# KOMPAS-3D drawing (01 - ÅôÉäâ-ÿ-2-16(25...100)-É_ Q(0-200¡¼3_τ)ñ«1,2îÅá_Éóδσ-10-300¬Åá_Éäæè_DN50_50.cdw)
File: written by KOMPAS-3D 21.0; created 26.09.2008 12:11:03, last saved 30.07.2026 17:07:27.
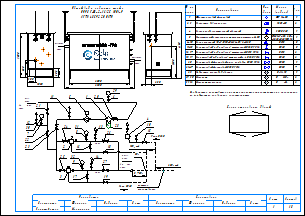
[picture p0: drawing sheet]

Sheets 1-2: A3, landscape

Document properties: Наименование: Макро:21; Автор: RaskoAdmin; Форматы листов документа: 2xA3; Полное имя файла: \\ur38nt01\Departments\КТО\КБ ПУРДГ\Заявки\Прайс-лист на типовые шкафы ГРПШ\ПУРДГ_стандарт_30_04_2026\ПУРДГ с РДСК\ПУРДГ-Ш-2-16(25...100)-Р_ Q(0-200нм3_ч)до1,2МПа_Рвых-10-300кПа_РДСК_DN50_50.cdw

Title block, sheet 1: Наименование: Пункт учета газа / ПУГ-Ш-400-Р / ЛГТИ.485922.001ТУ; designation: ЛГТИ.03.4411141; sheet number: 1; Количество листов документа: 2; organisation: ООО "ЭЛЬСТЕР Газэлектроника"; Форматы листов документа: A3; stored path: C:\Рабочие документы\Компас\ПУГ\Схема.cdw; Разработал: Устинов; Проверил: Кошкин; Утвердил: Кошкин
Title block, sheet 2: sheet number: 2; stored path: D:\Рабочие документы\Заявки\ПУРДГ\ПУРДГ-ШУЭО-2-100-Р 4411220.cdw; designation, second copy: ЛГТИ.03.4411141-

Views: Вид 1, Вид 2
Referenced files: wcvoit.frw
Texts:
  Normal
  № на
  схеме
  Усл.
  обозн.
  Марка
  (модель)
  Кол.
  Фильтр газовый фланцевый
  ФГ 16-50
  Регулятор давления газа
  РДСК-50
  Клапан предохранительный сбросной
  КПС DN20
  Измерительный комплекс с ротационным счетчиком Ду50
  СГ-ЭК-Р-(0,2...2,0)-
  Кран кнопочный VE-РАСКО-НЗ-1,6-G1/2-М20
  DN15
  Кран шаровой "под приварку" штуцерный DN20 PN16
  DN20
  Кран шаровой "под приварку" штуцерный DN15 PN16
  Кран шаровой "под приварку" штуцерный п/п DN20 PN16
  Кран шаровой фланцевый с мех. приводом DN50 PN16
  Кран шаровой фланцевый DN50 PN16
  DN50
  Индикатор перепада давления
  Манометр
  Манометр-напоромер
  Delta 15
  0...     МПа
  0...     кПа
  Общий вид и габариты шкафа
  ПУРДГ-Ш-2-16(25...100)-Р
  Выход газа
  Вход газа
  logo-rasko-ge.png
  DN 1
  местное
  сопротивление
  Римп DN20
  Выход
  газа
  Р=     кПа
  Вход
  Р=       МПа
  PDI
  Схема открывания дверей
  Предприятие изготовитель может заменять комплектующие на аналогичные,
  не ухудшающие заявленных характеристик.
  Должность
  Конструктор
  Фамилия
  Подпись
  Дата
  Согласовано
  Максимкин
  Лист
  Листов
  POLYLINE_STYLE_0.18_RGB_0_0_0
  POLYLINE_STYLE_0.50_RGB_0_0_0
  POLYLINE_STYLE_0.34_RGB_0_0_0
  PHANTOM_RGB_0_0_0_SC_1_THICK_0.18
  K5LT_THIN_RGB_0_0_0_THICK_0.18
  K5LT32769_RGB_0_0_0_THICK_0.18
  K5LT12_RGB_0_0_0_SC_1_THICK_0.18
  K5LT_DASHED_RGB_0_0_0_SC_1_THICK_0.18
  ACISOTGL_RGB_0_0_0_SC_0.8_THICK_0.25
  CONTINUOUS_RGB_0_127_31_THICK_0.3
  CONTINUOUS_RGB_0_0_255_THICK_0.35
  CONTINUOUS_RGB_255_0_0_THICK_0.35
  POLYLINE_STYLE_0.25_RGB_0_0_0
  CONTINUOUS_RGB_0_0_0_THICK_0.5
  POLYLINE_STYLE_0.35_RGB_0_0_255
  CONTINUOUS_RGB_0_0_0_THICK_0.4
  CONTINUOUS_RGB_0_0_0_THICK_0.35
  НЕВИДИМАЯ_RGB_0_0_0_SC_0.3_THICK_0.25
  СONTINUOUS_RGB_0_0_0_THICK_0.25
  ОСЕВАЯ2_RGB_248_153_30_SC_0.3_THICK_0.25
  Без оформления
Dimensions and other numbers on the sheet: 1; 2, 3; 2; 4; 5; 6-10; 11-15; 16, 17; 18, 19; 20; 21-27; 7; 28; 29, 30; 31, 32; 1500; 250; 300; 1050; 550; 305; 2000; 4130; 2300; 5,,,7DN 1; 30; 12; 21; 22; 23; 11; 6; 29; 24; 31; 8; 16; 13; 26; 18; 10; 15; 25; 32; 9; 3; 17; 14; 27; 19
